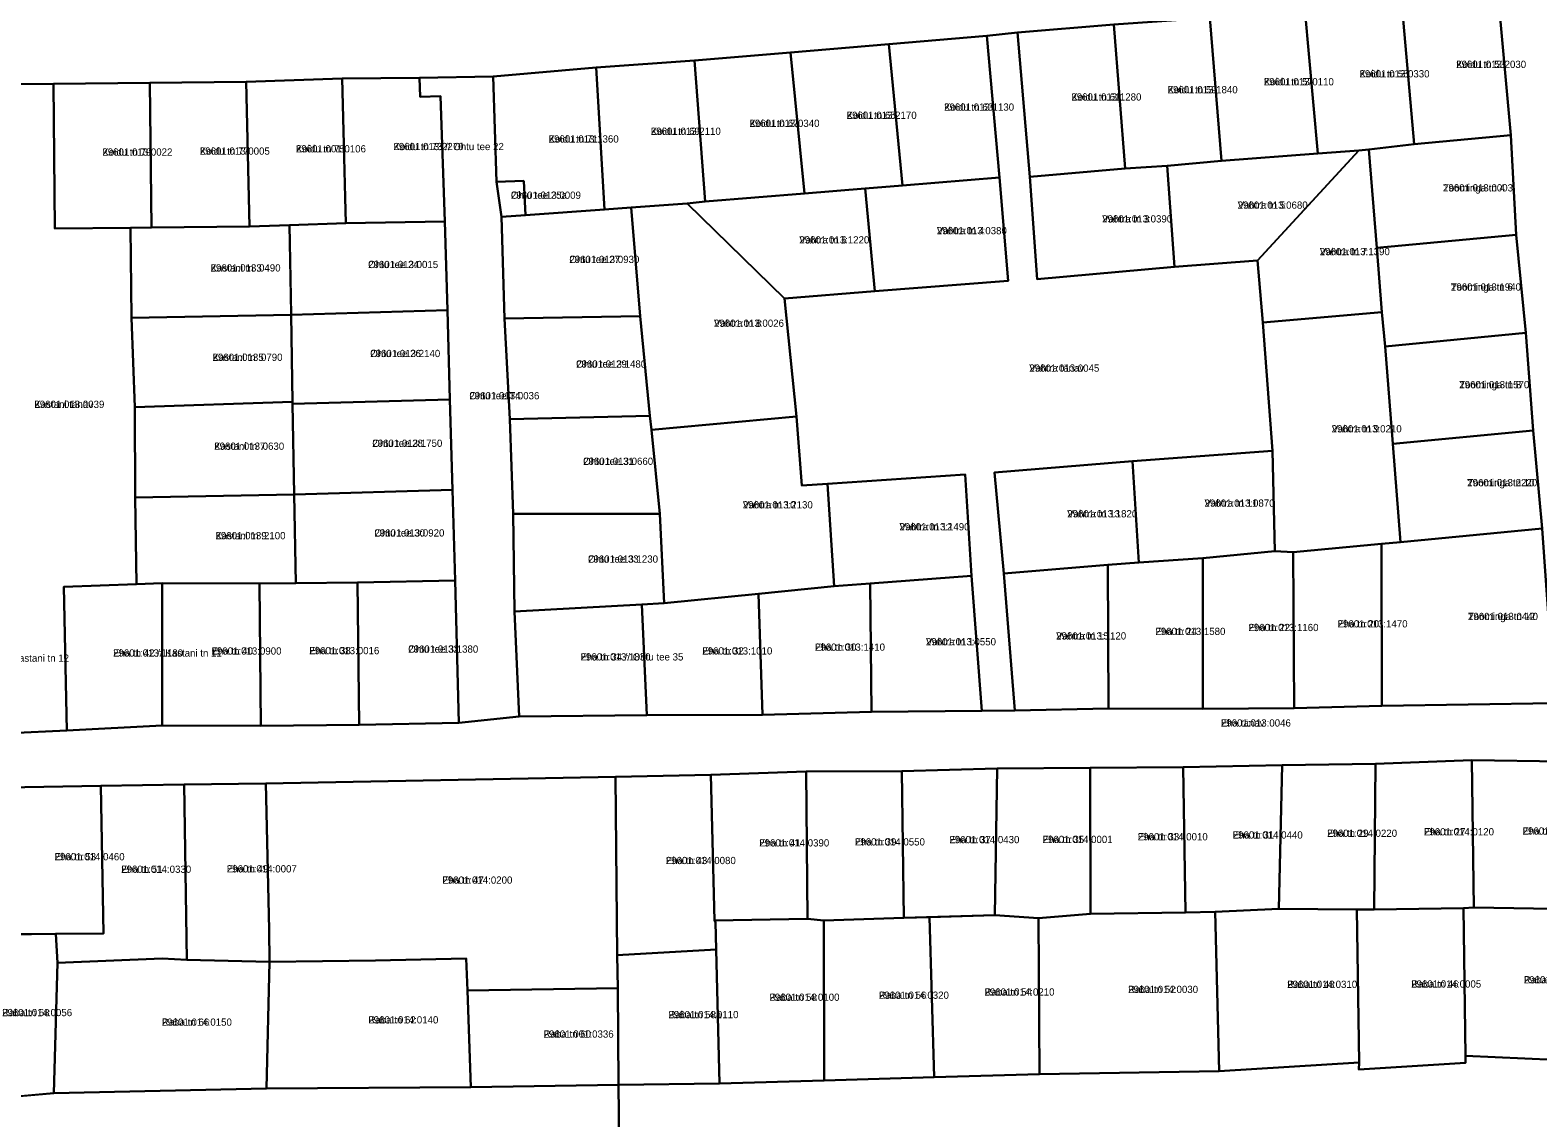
# Model space of a CAD drawing. Extents: x 518839 to 525192, y 6573164 to 6576561.
# Drawn here: x 523676 to 523988.3, y 6573652.7 to 6573878.1 of the extents above; entities that cross this region are included whole.
import ezdxf

# ---------------------------------------------------------------- set-up
doc = ezdxf.new("R2010")
doc.units = 0
for name, color, linetype in [('L_AADRESS', 7, 'Continuous'), ('PIIR', 7, 'Continuous'), ('TUNNUS', 7, 'Continuous')]:
    doc.layers.add(name, color=color, linetype=linetype)

msp = doc.modelspace()

# ---------------------------------------------------------------- linework, layer by layer
at = {"layer": 'PIIR'}
for points in [[(523991.91, 6573886.74), (523979.96, 6573886.04), (523960.05, 6573884.2), (523939.99, 6573882.39), (523920.33, 6573880.66), (523900.44, 6573879.28), (523880.51, 6573877.59), (523874.14, 6573876.88), (523853.82, 6573875.19), (523833.51, 6573873.42), (523813.6, 6573871.79), (523793.26, 6573870.36), (523771.87, 6573868.48), (523756.61, 6573868.23), (523740.59, 6573868.09), (523720.71, 6573867.39), (523700.81, 6573867.17), (523680.81, 6573866.98), (523669.79, 6573866.9)], [(523671.79, 6573732.4), (523683.56, 6573732.98), (523703.36, 6573733.98), (523723.8, 6573733.91), (523744.14, 6573734.13), (523764.78, 6573734.56), (523777.31, 6573735.87), (523803.7, 6573736.12), (523827.69, 6573736.21), (523850.25, 6573736.8), (523873.09, 6573737.03), (523879.91, 6573737.08), (523899.35, 6573737.49), (523918.89, 6573737.46), (523937.78, 6573737.6), (523955.98, 6573738.09), (523991.73, 6573738.64)], [(523993.31, 6573726.55), (523974.58, 6573726.83), (523954.63, 6573726.06), (523935.33, 6573725.8), (523914.81, 6573725.35), (523895.53, 6573725.21), (523876.26, 6573725.07), (523856.53, 6573724.52), (523836.69, 6573724.46), (523816.97, 6573723.79), (523797.21, 6573723.38), (523724.82, 6573721.96), (523707.9, 6573721.76), (523690.66, 6573721.47), (523670.95, 6573721.16)], [(523798.04, 6573641.63), (523797.87, 6573659.57), (523818.79, 6573659.82), (523840.47, 6573660.45), (523863.22, 6573661.1), (523885.08, 6573661.74), (523922.24, 6573662.37), (523951.24, 6573664.18), (523951.2, 6573662.75), (523973.32, 6573664.08), (523973.3, 6573665.56), (523997.88, 6573664.48)]]:
    msp.add_lwpolyline(points, dxfattribs=at)
for points in [[(523979.96, 6573886.04), (523991.91, 6573886.74), (523993.87, 6573855.18), (523998.29, 6573812.14), (523999.71, 6573790.43), (524001.71, 6573769.87), (524004.3, 6573740.13), (523991.73, 6573738.64), (523989.14, 6573774.8), (523987.31, 6573795.12), (523985.77, 6573815.38), (523983.8, 6573835.68), (523982.65, 6573856.32)], [(523939.99, 6573882.39), (523960.05, 6573884.2), (523962.69, 6573854.45), (523953.25, 6573853.38), (523951.2, 6573853.15), (523942.71, 6573852.51)], [(523960.05, 6573884.2), (523979.96, 6573886.04), (523982.65, 6573856.32), (523962.69, 6573854.45)], [(523902.82, 6573849.39), (523900.44, 6573879.28), (523920.33, 6573880.66), (523922.76, 6573850.99), (523911.47, 6573849.94)], [(523920.33, 6573880.66), (523939.99, 6573882.39), (523942.71, 6573852.51), (523922.76, 6573850.99)], [(523874.14, 6573876.88), (523880.51, 6573877.59), (523883.08, 6573847.7), (523884.56, 6573826.51), (523912.99, 6573829.02), (523930.22, 6573830.36), (523931.32, 6573817.54), (523933.31, 6573790.88), (523904.29, 6573788.75), (523875.72, 6573786.39), (523877.64, 6573765.48), (523879.91, 6573737.08), (523873.09, 6573737.03), (523870.97, 6573765.03), (523869.64, 6573785.99), (523841.14, 6573784.06), (523835.81, 6573783.73), (523834.74, 6573798), (523832.26, 6573822.48), (523850.97, 6573824.02), (523878.56, 6573826.17), (523876.76, 6573847.57)], [(523880.51, 6573877.59), (523900.44, 6573879.28), (523902.82, 6573849.39), (523883.08, 6573847.7)], [(523833.51, 6573873.42), (523853.82, 6573875.19), (523856.71, 6573845.92), (523848.92, 6573845.28), (523836.36, 6573844.27)], [(523853.82, 6573875.19), (523874.14, 6573876.88), (523876.76, 6573847.57), (523856.71, 6573845.92)], [(523813.6, 6573871.79), (523815.83, 6573842.58), (523812.08, 6573842.19), (523800.49, 6573841.32), (523794.92, 6573840.92), (523793.26, 6573870.36)], [(523813.6, 6573871.79), (523833.51, 6573873.42), (523836.36, 6573844.27), (523815.83, 6573842.58)], [(523721.45, 6573837.4), (523720.71, 6573867.39), (523740.59, 6573868.09), (523741.01, 6573851.67), (523741.22, 6573843.42), (523741.36, 6573838.1), (523729.69, 6573837.69)], [(523756.61, 6573868.23), (523756.8, 6573864.24), (523760.97, 6573864.43), (523761.88, 6573838.44), (523741.36, 6573838.1), (523741.22, 6573843.42), (523741.01, 6573851.67), (523740.59, 6573868.09)], [(523756.61, 6573868.23), (523771.87, 6573868.48), (523772.57, 6573846.64), (523773.62, 6573839.38), (523774.27, 6573818.34), (523775.32, 6573797.47), (523776.02, 6573777.85), (523776.32, 6573757.61), (523777.31, 6573735.87), (523764.78, 6573734.56), (523764, 6573764.05), (523763.45, 6573782.83), (523762.93, 6573801.58), (523762.4, 6573820.04), (523761.88, 6573838.44), (523760.97, 6573864.43), (523756.8, 6573864.24)], [(523778.25, 6573846.87), (523772.57, 6573846.64), (523771.87, 6573868.48), (523793.26, 6573870.36), (523794.92, 6573840.92), (523778.58, 6573839.74)], [(523669.79, 6573866.9), (523680.81, 6573866.98), (523681.09, 6573836.98), (523696.74, 6573837.13), (523697, 6573818.44), (523697.67, 6573799.99), (523697.75, 6573781.23), (523698.04, 6573763.28), (523682.95, 6573762.72), (523683.56, 6573732.98), (523671.79, 6573732.4), (523671.24, 6573762.39), (523656.86, 6573762.12), (523656.77, 6573780.37), (523656.38, 6573798.96), (523655.8, 6573817.24), (523655.68, 6573836.78), (523670.33, 6573836.83)], [(523680.81, 6573866.98), (523700.81, 6573867.17), (523701.09, 6573837.17), (523696.74, 6573837.13), (523681.09, 6573836.98)], [(523720.71, 6573867.39), (523721.45, 6573837.4), (523701.09, 6573837.17), (523700.81, 6573867.17)], [(523953.25, 6573853.38), (523962.69, 6573854.45), (523982.65, 6573856.32), (523983.8, 6573835.68), (523954.9, 6573833)], [(523912.99, 6573829.02), (523911.47, 6573849.94), (523922.76, 6573850.99), (523942.71, 6573852.51), (523951.2, 6573853.15), (523930.22, 6573830.36)], [(523951.2, 6573853.15), (523953.25, 6573853.38), (523954.9, 6573833), (523955.99, 6573819.65), (523931.32, 6573817.54), (523930.22, 6573830.36)], [(523883.08, 6573847.7), (523902.82, 6573849.39), (523911.47, 6573849.94), (523912.99, 6573829.02), (523884.56, 6573826.51)], [(523778.25, 6573846.87), (523778.58, 6573839.74), (523773.62, 6573839.38), (523772.57, 6573846.64)], [(523848.92, 6573845.28), (523856.71, 6573845.92), (523876.76, 6573847.57), (523878.56, 6573826.17), (523850.97, 6573824.02)], [(523812.08, 6573842.19), (523815.83, 6573842.58), (523836.36, 6573844.27), (523848.92, 6573845.28), (523850.97, 6573824.02), (523832.26, 6573822.48)], [(523773.62, 6573839.38), (523778.58, 6573839.74), (523794.92, 6573840.92), (523800.49, 6573841.32), (523802.33, 6573818.82), (523774.27, 6573818.34)], [(523800.49, 6573841.32), (523812.08, 6573842.19), (523832.26, 6573822.48), (523834.74, 6573798), (523804.69, 6573795.24), (523804.36, 6573798.14), (523802.33, 6573818.82)], [(523729.69, 6573837.69), (523730.02, 6573819.11), (523697, 6573818.44), (523696.74, 6573837.13), (523701.09, 6573837.17), (523721.45, 6573837.4)], [(523761.88, 6573838.44), (523762.4, 6573820.04), (523730.02, 6573819.11), (523730.02, 6573819.45), (523729.69, 6573837.69), (523741.36, 6573838.1)], [(523955.99, 6573819.65), (523954.9, 6573833), (523983.8, 6573835.68), (523985.77, 6573815.38), (523956.67, 6573812.54)], [(523697.67, 6573799.99), (523697, 6573818.44), (523730.02, 6573819.11), (523730.35, 6573801.04)], [(523762.4, 6573820.04), (523762.93, 6573801.58), (523730.36, 6573800.64), (523730.35, 6573801.04), (523730.02, 6573819.11)], [(523774.27, 6573818.34), (523802.33, 6573818.82), (523804.36, 6573798.14), (523775.32, 6573797.47)], [(523933.83, 6573770.1), (523933.31, 6573790.88), (523931.32, 6573817.54), (523955.99, 6573819.65), (523956.67, 6573812.54), (523958.25, 6573792.38), (523959.83, 6573772.02), (523955.88, 6573771.65), (523937.61, 6573769.95)], [(523956.67, 6573812.54), (523985.77, 6573815.38), (523987.31, 6573795.12), (523958.25, 6573792.38)], [(523697.67, 6573799.99), (523730.35, 6573801.04), (523730.36, 6573800.64), (523730.68, 6573781.89), (523697.75, 6573781.23)], [(523763.45, 6573782.83), (523730.68, 6573781.89), (523730.36, 6573800.64), (523762.93, 6573801.58)], [(523775.32, 6573797.47), (523804.36, 6573798.14), (523804.69, 6573795.24), (523806.42, 6573777.86), (523776.02, 6573777.85)], [(523806.42, 6573777.86), (523804.69, 6573795.24), (523834.74, 6573798), (523835.81, 6573783.73), (523841.14, 6573784.06), (523842.49, 6573762.87), (523826.84, 6573761.31), (523807.31, 6573759.33)], [(523958.25, 6573792.38), (523987.31, 6573795.12), (523989.14, 6573774.8), (523959.83, 6573772.02)], [(523905.61, 6573767.79), (523904.29, 6573788.75), (523933.31, 6573790.88), (523933.83, 6573770.1), (523918.89, 6573768.69)], [(523875.72, 6573786.39), (523904.29, 6573788.75), (523905.61, 6573767.79), (523899.23, 6573767.26), (523877.64, 6573765.48)], [(523842.49, 6573762.87), (523841.14, 6573784.06), (523869.64, 6573785.99), (523870.97, 6573765.03), (523849.98, 6573763.44)], [(523698.04, 6573763.28), (523697.75, 6573781.23), (523730.68, 6573781.89), (523731.04, 6573763.49), (523723.48, 6573763.41), (523703.31, 6573763.48)], [(523731.04, 6573763.49), (523730.68, 6573781.89), (523763.45, 6573782.83), (523764, 6573764.05), (523743.82, 6573763.63)], [(523776.02, 6573777.85), (523806.42, 6573777.86), (523807.31, 6573759.33), (523802.7, 6573759.07), (523776.32, 6573757.61)], [(523991.73, 6573738.64), (523955.98, 6573738.09), (523955.88, 6573771.65), (523959.83, 6573772.02), (523989.14, 6573774.8)], [(523937.61, 6573769.95), (523955.88, 6573771.65), (523955.98, 6573738.09), (523937.78, 6573737.6)], [(523899.23, 6573767.26), (523905.61, 6573767.79), (523918.89, 6573768.69), (523918.89, 6573737.46), (523899.35, 6573737.49)], [(523933.83, 6573770.1), (523937.61, 6573769.95), (523937.78, 6573737.6), (523918.89, 6573737.46), (523918.89, 6573768.69)], [(523870.97, 6573765.03), (523873.09, 6573737.03), (523850.25, 6573736.8), (523849.98, 6573763.44)], [(523877.64, 6573765.48), (523899.23, 6573767.26), (523899.35, 6573737.49), (523879.91, 6573737.08)], [(523682.95, 6573762.72), (523698.04, 6573763.28), (523703.31, 6573763.48), (523703.36, 6573733.98), (523683.56, 6573732.98)], [(523703.31, 6573763.48), (523723.48, 6573763.41), (523723.8, 6573733.91), (523703.36, 6573733.98)], [(523743.82, 6573763.63), (523744.14, 6573734.13), (523723.8, 6573733.91), (523723.48, 6573763.41), (523731.04, 6573763.49)], [(523743.82, 6573763.63), (523764, 6573764.05), (523764.78, 6573734.56), (523744.14, 6573734.13)], [(523826.84, 6573761.31), (523842.49, 6573762.87), (523849.98, 6573763.44), (523850.25, 6573736.8), (523827.69, 6573736.21)], [(523776.32, 6573757.61), (523802.7, 6573759.07), (523803.7, 6573736.12), (523777.31, 6573735.87)], [(523803.7, 6573736.12), (523802.7, 6573759.07), (523807.31, 6573759.33), (523826.84, 6573761.31), (523827.69, 6573736.21)], [(523816.97, 6573723.79), (523836.69, 6573724.46), (523837.03, 6573693.91), (523817.77, 6573693.58)], [(523837.03, 6573693.91), (523836.69, 6573724.46), (523856.53, 6573724.52), (523856.96, 6573694.13), (523840.35, 6573693.58)], [(523856.53, 6573724.52), (523876.26, 6573725.07), (523875.77, 6573694.72), (523856.96, 6573694.13)], [(523876.26, 6573725.07), (523895.53, 6573725.21), (523895.62, 6573695), (523884.84, 6573694.08), (523875.77, 6573694.72)], [(523895.53, 6573725.21), (523914.81, 6573725.35), (523915.27, 6573695.23), (523895.62, 6573695)], [(523915.27, 6573695.23), (523914.81, 6573725.35), (523935.33, 6573725.8), (523934.62, 6573696.01), (523921.45, 6573695.41)], [(523935.33, 6573725.8), (523954.63, 6573726.06), (523954.35, 6573695.88), (523950.75, 6573695.9), (523934.62, 6573696.01)], [(523954.63, 6573726.06), (523974.58, 6573726.83), (523975.03, 6573696.27), (523972.87, 6573696.12), (523954.35, 6573695.88)], [(523974.58, 6573726.83), (523993.31, 6573726.55), (523995.65, 6573695.93), (523975.03, 6573696.27)], [(523690.66, 6573721.47), (523691.16, 6573690.92), (523671.2, 6573690.74), (523670.95, 6573721.16)], [(523681.28, 6573690.84), (523691.16, 6573690.92), (523690.66, 6573721.47), (523707.9, 6573721.76), (523708.41, 6573685.43), (523703.35, 6573685.75), (523681.65, 6573684.84)], [(523724.82, 6573721.96), (523725.52, 6573691.7), (523725.55, 6573685.03), (523708.41, 6573685.43), (523707.9, 6573721.76)], [(523797.21, 6573723.38), (523797.61, 6573686.4), (523797.68, 6573679.57), (523766.57, 6573679.06), (523766.32, 6573685.74), (523747.55, 6573685.3), (523725.55, 6573685.03), (523725.52, 6573691.7), (523724.82, 6573721.96)], [(523797.21, 6573723.38), (523816.97, 6573723.79), (523817.77, 6573693.58), (523817.95, 6573693.27), (523818.09, 6573687.56), (523797.61, 6573686.4)], [(523954.35, 6573695.88), (523972.87, 6573696.12), (523973.3, 6573665.56), (523973.32, 6573664.08), (523951.2, 6573662.75), (523951.24, 6573664.18), (523950.75, 6573695.9)], [(523972.87, 6573696.12), (523975.03, 6573696.27), (523995.65, 6573695.93), (523997.88, 6573664.48), (523973.3, 6573665.56)], [(523818.09, 6573687.56), (523817.95, 6573693.27), (523817.77, 6573693.58), (523837.03, 6573693.91), (523840.35, 6573693.58), (523840.47, 6573660.45), (523818.79, 6573659.82)], [(523840.35, 6573693.58), (523856.96, 6573694.13), (523862.24, 6573694.31), (523863.22, 6573661.1), (523840.47, 6573660.45)], [(523862.24, 6573694.31), (523875.77, 6573694.72), (523884.84, 6573694.08), (523885.08, 6573661.74), (523863.22, 6573661.1)], [(523884.84, 6573694.08), (523895.62, 6573695), (523915.27, 6573695.23), (523921.45, 6573695.41), (523922.24, 6573662.37), (523885.08, 6573661.74)], [(523921.45, 6573695.41), (523934.62, 6573696.01), (523950.75, 6573695.9), (523951.24, 6573664.18), (523922.24, 6573662.37)], [(523659.29, 6573690.4), (523671.2, 6573690.7), (523681.28, 6573690.84), (523681.65, 6573684.84), (523680.91, 6573657.85), (523658.7, 6573655.81)], [(523797.68, 6573679.57), (523797.61, 6573686.4), (523818.09, 6573687.56), (523818.79, 6573659.82), (523797.87, 6573659.57)], [(523681.65, 6573684.84), (523703.35, 6573685.75), (523708.41, 6573685.43), (523725.55, 6573685.03), (523724.95, 6573658.79), (523680.89, 6573657.84)], [(523725.55, 6573685.03), (523747.55, 6573685.3), (523766.32, 6573685.74), (523766.57, 6573679.06), (523767.3, 6573659.07), (523724.95, 6573658.79)], [(523766.57, 6573679.06), (523797.68, 6573679.57), (523797.87, 6573659.57), (523767.3, 6573659.07)], [(523593.49, 6573636.97), (523593.28, 6573655.92), (523615.49, 6573656.39), (523635.86, 6573656.13), (523658.64, 6573655.87), (523680.91, 6573657.85), (523724.95, 6573658.79), (523767.3, 6573659.07), (523797.87, 6573659.57), (523798.04, 6573641.63), (523731.73, 6573638.73), (523716.85, 6573638.54), (523702.51, 6573638.35), (523682.5, 6573638.09), (523633.32, 6573637.47)]]:
    msp.add_lwpolyline(points, close=True, dxfattribs=at)

# ---------------------------------------------------------------- texts
at = {"layer": 'L_AADRESS'}
for s, p in [('Koidu tn 53', (523971.35, 6573870.25)), ('Koidu tn 57', (523931.52, 6573866.65)), ('Koidu tn 55', (523951.34, 6573868.29)), ('Koidu tn 61', (523891.66, 6573863.49)), ('Koidu tn 59', (523911.6, 6573865)), ('Koidu tn 63', (523865.29, 6573861.39)), ('Koidu tn 67', (523824.98, 6573858.03)), ('Koidu tn 65', (523845.11, 6573859.7)), ('Koidu tn 71', (523783.39, 6573854.79)), ('Koidu tn 69', (523804.54, 6573856.39)), ('Koidu tn 79', (523690.95, 6573852.08)), ('Koidu tn 77', (523711.13, 6573852.28)), ('Koidu tn 75', (523731.04, 6573852.75)), ('Koidu tn 73 // Ohtu tee 22', (523751.24, 6573853.22)), ('Toominga tn 4', (523968.63, 6573844.66)), ('Ohtu tee 25a', (523775.57, 6573843.14)), ('Vahtra tn 3', (523898.03, 6573838.23)), ('Vahtra tn 5', (523926.1, 6573841.08)), ('Vahtra tn 4', (523863.79, 6573835.79)), ('Vahtra tn 6', (523835.3, 6573833.88)), ('Ohtu tee 24', (523746, 6573828.78)), ('Ohtu tee 27', (523787.67, 6573829.83)), ('Vahtra tn 7', (523943.11, 6573831.45)), ('Kastani tn 3', (523713.36, 6573828.07)), ('Toominga tn 6', (523970.27, 6573824.11)), ('Vahtra tn 8', (523817.62, 6573816.61)), ('Ohtu tee 26', (523746.43, 6573810.34)), ('Kastani tn 5', (523713.76, 6573809.55)), ('Ohtu tee 29', (523789.08, 6573808.15)), ('Vahtra tänav', (523882.94, 6573807.31)), ('Toominga tn 8', (523972, 6573803.88)), ('Ohtu tee T4', (523766.96, 6573801.59)), ('Kastani tänav', (523676.86, 6573799.8)), ('Vahtra tn 9', (523945.57, 6573794.73)), ('Ohtu tee 28', (523746.86, 6573791.74)), ('Kastani tn 7', (523714.11, 6573791.13)), ('Ohtu tee 31', (523790.53, 6573788)), ('Toominga tn 10', (523973.64, 6573783.57)), ('Vahtra tn 10', (523823.59, 6573778.98)), ('Vahtra tn 11', (523919.24, 6573779.33)), ('Vahtra tn 13', (523890.8, 6573777.12)), ('Kastani tn 9', (523714.38, 6573772.59)), ('Ohtu tee 30', (523747.29, 6573773.16)), ('Vahtra tn 12', (523856.06, 6573774.43)), ('Ohtu tee 33', (523791.54, 6573767.74)), ('Eha tn 20', (523946.79, 6573754.32)), ('Toominga tn 12', (523973.8, 6573755.85)), ('Vahtra tn 15', (523888.5, 6573751.82)), ('Eha tn 24', (523909.06, 6573752.75)), ('Eha tn 22', (523928.34, 6573753.56)), ('Eha tn 42 // Kastani tn 11', (523693.16, 6573748.28)), ('Eha tn 40', (523713.55, 6573748.69)), ('Eha tn 38', (523733.81, 6573748.77)), ('Ohtu tee 32', (523754.3, 6573749.09)), ('Eha tn 32', (523815.21, 6573748.71)), ('Eha tn 30', (523838.55, 6573749.49)), ('Vahtra tn 14', (523861.54, 6573750.61)), ('Eha tn 44 // Kastani tn 12', (523661.52, 6573747.21)), ('Eha tn 34 // Ohtu tee 35', (523789.99, 6573747.47)), ('Eha tänav', (523922.62, 6573733.78)), ('Eha tn 33', (523905.4, 6573710.2)), ('Eha tn 31', (523925.07, 6573710.57)), ('Eha tn 29', (523944.62, 6573710.93)), ('Eha tn 27', (523964.69, 6573711.23)), ('Eha tn 25', (523985.11, 6573711.39)), ('Eha tn 41', (523827, 6573708.93)), ('Eha tn 39', (523846.82, 6573709.14)), ('Eha tn 37', (523866.39, 6573709.61)), ('Eha tn 35', (523885.7, 6573709.65)), ('Eha tn 53', (523681.05, 6573706.07)), ('Eha tn 43', (523807.65, 6573705.28)), ('Eha tn 51', (523694.84, 6573703.47)), ('Eha tn 49', (523716.72, 6573703.55)), ('Eha tn 47', (523761.37, 6573701.22)), ('Raba tn 48', (523936.35, 6573679.62)), ('Raba tn 46', (523962.04, 6573679.69)), ('Raba tn 44', (523985.38, 6573680.56)), ('Raba tn 58', (523829.12, 6573676.95)), ('Raba tn 56', (523851.79, 6573677.37)), ('Raba tn 54', (523873.66, 6573678.03)), ('Raba tn 52', (523903.4, 6573678.57)), ('Raba tn 68', (523670.18, 6573673.77)), ('Raba tn 58a', (523808.2, 6573673.35)), ('Raba tn 66', (523703.27, 6573671.79)), ('Raba tn 62', (523746.04, 6573672.26)), ('Raba tn 60', (523782.35, 6573669.32))]:
    msp.add_text(s, height=1.5, dxfattribs=at).set_placement(p)
at = {"layer": 'TUNNUS'}
for s, p in [('29601:013:2030', (523971.35, 6573870.25)), ('29601:013:0110', (523931.52, 6573866.65)), ('29601:013:0330', (523951.34, 6573868.29)), ('29601:013:1280', (523891.66, 6573863.49)), ('29601:013:1840', (523911.6, 6573865)), ('29601:013:1130', (523865.29, 6573861.39)), ('29601:013:0340', (523824.98, 6573858.03)), ('29601:013:2170', (523845.11, 6573859.7)), ('29601:013:1360', (523783.39, 6573854.79)), ('29601:013:2110', (523804.54, 6573856.39)), ('29601:013:0022', (523690.95, 6573852.08)), ('29601:013:0005', (523711.13, 6573852.28)), ('29601:001:0106', (523731.04, 6573852.75)), ('29601:013:2270', (523751.24, 6573853.22)), ('29601:013:0003', (523968.63, 6573844.66)), ('29601:013:0009', (523775.57, 6573843.14)), ('29601:013:0390', (523898.03, 6573838.23)), ('29601:013:0680', (523926.1, 6573841.08)), ('29601:013:0380', (523863.79, 6573835.79)), ('29601:013:1220', (523835.3, 6573833.88)), ('29601:013:0930', (523787.67, 6573829.83)), ('29601:013:1390', (523943.11, 6573831.45)), ('29601:013:0490', (523713.36, 6573828.07)), ('29601:013:0015', (523746, 6573828.78)), ('29601:013:1940', (523970.27, 6573824.11)), ('29601:013:0026', (523817.62, 6573816.61)), ('29601:013:2140', (523746.43, 6573810.34)), ('29601:013:0790', (523713.76, 6573809.55)), ('29601:013:1480', (523789.08, 6573808.15)), ('29601:013:0045', (523882.94, 6573807.31)), ('29601:013:1570', (523972, 6573803.88)), ('29601:013:0036', (523766.96, 6573801.59)), ('29601:013:0039', (523676.86, 6573799.8)), ('29601:013:0210', (523945.57, 6573794.73)), ('29601:013:1750', (523746.86, 6573791.74)), ('29601:013:0630', (523714.11, 6573791.13)), ('29601:013:0660', (523790.53, 6573788)), ('29601:013:2220', (523973.64, 6573783.57)), ('29601:013:2130', (523823.59, 6573778.98)), ('29601:013:0870', (523919.24, 6573779.33)), ('29601:013:1820', (523890.8, 6573777.12)), ('29601:013:0920', (523747.29, 6573773.16)), ('29601:013:1490', (523856.06, 6573774.43)), ('29601:013:2100', (523714.38, 6573772.59)), ('29601:013:1230', (523791.54, 6573767.74)), ('29601:013:1470', (523946.79, 6573754.32)), ('29601:013:0440', (523973.8, 6573755.85)), ('29601:013:1120', (523888.5, 6573751.82)), ('29601:013:1580', (523909.06, 6573752.75)), ('29601:013:1160', (523928.34, 6573753.56)), ('29601:013:1180', (523693.16, 6573748.28)), ('29601:013:0900', (523713.55, 6573748.69)), ('29601:013:0016', (523733.81, 6573748.77)), ('29601:013:1380', (523754.3, 6573749.09)), ('29601:013:1010', (523815.21, 6573748.71)), ('29601:013:1410', (523838.55, 6573749.49)), ('29601:013:0550', (523861.54, 6573750.61)), ('29601:013:1830', (523789.99, 6573747.47)), ('29601:013:0046', (523922.62, 6573733.78)), ('29601:014:0010', (523905.4, 6573710.2)), ('29601:014:0440', (523925.07, 6573710.57)), ('29601:014:0220', (523944.62, 6573710.93)), ('29601:014:0120', (523964.69, 6573711.23)), ('29601:014:0003', (523985.11, 6573711.39)), ('29601:014:0390', (523827, 6573708.93)), ('29601:014:0550', (523846.82, 6573709.14)), ('29601:014:0430', (523866.39, 6573709.61)), ('29601:014:0001', (523885.7, 6573709.65)), ('29601:014:0460', (523681.05, 6573706.07)), ('29601:014:0080', (523807.65, 6573705.28)), ('29601:014:0330', (523694.84, 6573703.47)), ('29601:014:0007', (523716.72, 6573703.55)), ('29601:014:0200', (523761.37, 6573701.22)), ('29601:014:0310', (523936.35, 6573679.62)), ('29601:014:0005', (523962.04, 6573679.69)), ('29601:014:0300', (523985.38, 6573680.56)), ('29601:014:0100', (523829.12, 6573676.95)), ('29601:014:0320', (523851.79, 6573677.37)), ('29601:014:0210', (523873.66, 6573678.03)), ('29601:014:0030', (523903.4, 6573678.57)), ('29601:014:0056', (523670.18, 6573673.77)), ('29601:014:0110', (523808.2, 6573673.35)), ('29601:014:0150', (523703.27, 6573671.79)), ('29601:014:0140', (523746.04, 6573672.26)), ('29601:001:0336', (523782.35, 6573669.32))]:
    msp.add_text(s, height=1.5, dxfattribs=at).set_placement(p)

doc.saveas('drawing.dxf')
